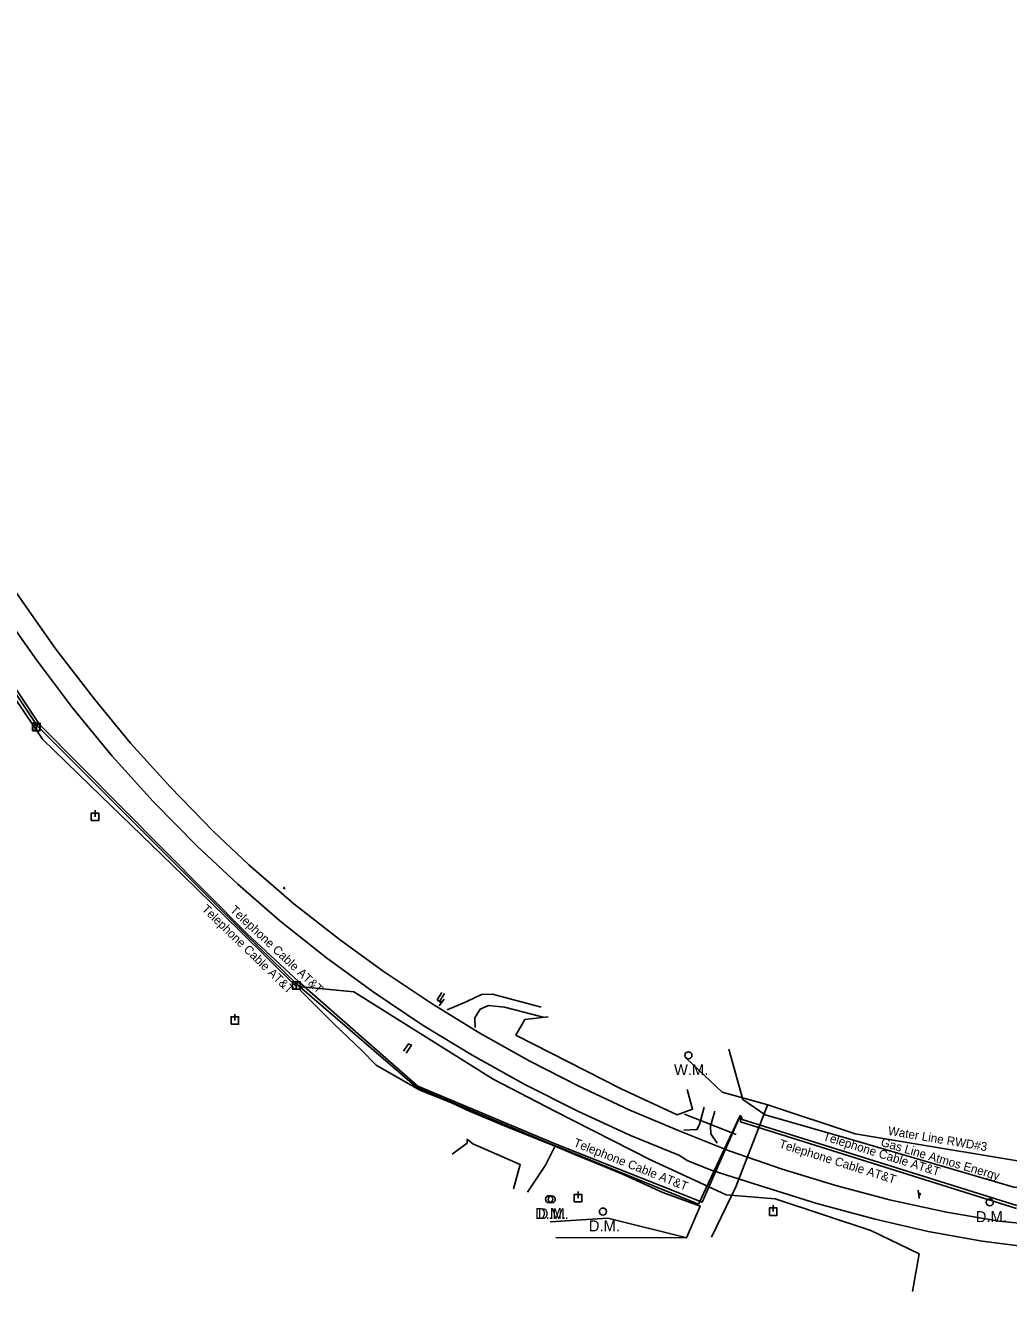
# Model space of a CAD drawing. Extents: x 19405533 to 19432306, y 137070 to 200991.
# Drawn here: x 19429869 to 19430925, y 137298 to 138658 of the extents above; entities that cross this region are included whole.
import ezdxf

# ---------------------------------------------------------------- set-up
doc = ezdxf.new("R2010")
doc.units = 0
for name, color, linetype in [('sv_Drainage Structures_x_s', 7, 'Continuous'), ('sv_Fence Existing_x_s', 7, 'Continuous'), ('sv_Gas Utility Label_x_n', 7, 'Continuous'), ('sv_Gas Utility_x_n', 7, 'Continuous'), ('sv_Pavement Edge_x_s', 7, 'Continuous'), ('sv_Poles Utility_x_n', 7, 'Continuous'), ('sv_Private Road_x_s', 7, 'Continuous'), ('sv_Signs Billboards_x_s', 7, 'Continuous'), ('sv_Slope Lines_x_s', 7, 'Continuous'), ('sv_Telephone Line Label_x_n', 7, 'Continuous'), ('sv_Telephone Line_x_n', 7, 'Continuous'), ('sv_Treeline_x_s', 7, 'Continuous'), ('sv_Water Line Label_x_n', 7, 'Continuous'), ('sv_Water Line_x_n', 7, 'Continuous'), ('sv_Waters Edge_x_s', 7, 'Continuous')]:
    doc.layers.add(name, color=color, linetype=linetype)

msp = doc.modelspace()

# ---------------------------------------------------------------- linework, layer by layer
at = {"layer": 'sv_Drainage Structures_x_s'}
msp.add_line((19430632.3, 137466.8), (19430577, 137488.7), dxfattribs=at)
for points in [[(19430147.7, 137732.2), (19430146.7, 137732.1), (19430146.8, 137730.9), (19430148, 137731.1)], [(19430147.7, 137732.2), (19430146.7, 137732.1), (19430146.8, 137730.9), (19430148, 137731.1)], [(19430147.7, 137732.2), (19430146.7, 137732.1), (19430146.8, 137730.9), (19430148, 137731.1)], [(19430319.3, 137618.4), (19430313.9, 137609.8), (19430311.4, 137611.5), (19430316.2, 137619.4)], [(19430319.3, 137618.4), (19430313.9, 137609.8), (19430311.4, 137611.5), (19430316.2, 137619.4)], [(19430319.3, 137618.4), (19430313.9, 137609.8), (19430311.4, 137611.5), (19430316.2, 137619.4)], [(19430275.1, 137556.2), (19430280.6, 137564.3), (19430283.7, 137562.9), (19430278.1, 137554.3)]]:
    msp.add_lwpolyline(points, dxfattribs=at)
at = {"layer": 'sv_Fence Existing_x_s'}
msp.add_line((19430438.8, 137356), (19430579.5, 137355.6), dxfattribs=at)
for points in [[(19430161.1, 137624.8), (19430099.2, 137685.4), (19430038.4, 137744.9), (19429938.2, 137841.9), (19429887.5, 137891.4), (19429856.8, 137936.6), (19429776.8, 138056.5), (19429730.3, 138127.7)], [(19430162.4, 137623.5), (19430200.2, 137585.8), (19430229.9, 137557.4), (19430245.9, 137541.3), (19430292.7, 137514.5), (19430326.6, 137500.8), (19430326.6, 137500.8), (19430346.7, 137491.4), (19430388, 137474.2), (19430417.3, 137462.5), (19430438, 137454.2), (19430458.2, 137445.8), (19430480.9, 137436.2), (19430509.7, 137424.5), (19430553.8, 137404.4), (19430593.8, 137389.9), (19430579.3, 137355.7)]]:
    msp.add_lwpolyline(points, dxfattribs=at)
at = {"layer": 'sv_Gas Utility_x_n'}
msp.add_lwpolyline([(19432037.6, 137379.6), (19431571.4, 137393.9), (19430996.6, 137402.9), (19430930.7, 137410.1), (19430758.5, 137460.5), (19430663.5, 137488), (19430639.7, 137504.2), (19430624.7, 137558.5)], dxfattribs=at)
msp.add_lwpolyline([(19432037.6, 137379.6), (19431571.4, 137393.9), (19430996.6, 137402.9), (19430930.7, 137410.1), (19430758.5, 137460.5), (19430663.5, 137488), (19430639.7, 137504.2), (19430624.7, 137558.5)], dxfattribs=at)
msp.add_lwpolyline([(19432037.6, 137379.6), (19431571.4, 137393.9), (19430996.6, 137402.9), (19430930.7, 137410.1), (19430758.5, 137460.5), (19430663.5, 137488), (19430639.7, 137504.2), (19430624.7, 137558.5)], dxfattribs=at)
at = {"layer": 'sv_Pavement Edge_x_s'}
for points in [[(19429459.1, 138633.6), (19429496.2, 138578.8), (19429532.9, 138525), (19429569.7, 138471.2), (19429607.7, 138415.4), (19429642, 138365.4), (19429644.7, 138364), (19429686.6, 138301.7), (19429688.3, 138297.5), (19429724.6, 138242.8), (19429763.6, 138186.4), (19429792.8, 138143.7), (19429829.4, 138091.6), (19429865.5, 138039.6), (19429901.9, 137988.3), (19429943.3, 137934.4), (19429982.1, 137887.3), (19430024.5, 137840.1), (19430070.7, 137792.6), (19430109, 137756.6)], [(19430053.5, 137776.4), (19430006.1, 137824.5), (19429962.2, 137873.1), (19429919.8, 137925), (19429881, 137976.7), (19429843.6, 138029.5), (19429805, 138084.7), (19429774.6, 138127.7), (19429764.8, 138139.4), (19429738.2, 138178.1), (19429735.7, 138184.8), (19429699.6, 138238.3), (19429665.1, 138289.8), (19429624.4, 138349.5), (19429586.7, 138404.5), (19429549.8, 138458.9), (19429515.2, 138509.9), (19429480.2, 138560.9), (19429438.8, 138621.4)], [(19430955.9, 137344.5), (19430896.8, 137352.3), (19430838.8, 137362.5), (19430781.7, 137375.7), (19430719.1, 137392.7), (19430658.5, 137411.6), (19430606.8, 137428), (19430580.7, 137438.5), (19430570.8, 137444.4), (19430519, 137465.7), (19430462.3, 137491.8), (19430404.6, 137520.8), (19430349.7, 137551.8), (19430296.3, 137584), (19430242.5, 137620.2), (19430192.6, 137656.7), (19430142.4, 137696.4), (19430097.1, 137735.7), (19430053.5, 137776.4)], [(19430109, 137756.6), (19430157.5, 137714.6), (19430207.6, 137675.6), (19430253.3, 137642.2), (19430306.1, 137607), (19430357.3, 137575.5), (19430410.8, 137545.6), (19430462.6, 137519.1), (19430518.1, 137492.8), (19430571.1, 137470.7), (19430625.1, 137449.2), (19430682, 137429.6), (19430739.6, 137411.9), (19430797.1, 137396.7), (19430858.3, 137383.3), (19430914.9, 137373.7), (19430957.8, 137369.5)]]:
    msp.add_lwpolyline(points, dxfattribs=at)
at = {"layer": 'sv_Poles Utility_x_n'}
for p, q in [((19429939.8, 137812), (19429939.9, 137812.1)), ((19429943.8, 137808.1), (19429943.8, 137815.1)), ((19430090, 137593.1), (19430090.1, 137593.2)), ((19430094, 137589.2), (19430094, 137596.2)), ((19430458.6, 137402.3), (19430458.7, 137402.4)), ((19430462.6, 137398.4), (19430462.6, 137405.5)), ((19430668.3, 137387.7), (19430668.4, 137387.8)), ((19430672.3, 137383.9), (19430672.3, 137390.9))]:
    msp.add_line(p, q, dxfattribs=at)
for points in [[(19429939.8, 137804.1), (19429947.8, 137804.1), (19429947.8, 137812.1), (19429939.8, 137812.1)], [(19430090, 137585.2), (19430098, 137585.2), (19430098, 137593.2), (19430090, 137593.2)], [(19430458.6, 137394.4), (19430466.6, 137394.4), (19430466.6, 137402.4), (19430458.6, 137402.4)], [(19430668.3, 137379.8), (19430676.3, 137379.8), (19430676.3, 137387.8), (19430668.3, 137387.8)]]:
    msp.add_lwpolyline(points, close=True, dxfattribs=at)
for centre in [(19430431.6, 137397.2), (19430434.4, 137397.1), (19430489.3, 137384), (19430904.9, 137393.9)]:
    msp.add_circle(centre, 3.78, dxfattribs=at)
at = {"layer": 'sv_Private Road_x_s'}
for points in [[(19430422.9, 137603.7), (19430370.8, 137617.4), (19430359, 137617.1), (19430343.3, 137609.6), (19430322.1, 137600.6)], [(19430422.9, 137603.7), (19430370.8, 137617.4), (19430359, 137617.1), (19430343.3, 137609.6), (19430322.1, 137600.6)], [(19430422.9, 137603.7), (19430370.8, 137617.4), (19430359, 137617.1), (19430343.3, 137609.6), (19430322.1, 137600.6)], [(19430352, 137581.7), (19430351.8, 137592.1), (19430357.4, 137601.5), (19430366.5, 137605.5), (19430383.8, 137603.5), (19430425, 137592.7)], [(19430352, 137581.7), (19430351.8, 137592.1), (19430357.4, 137601.5), (19430366.5, 137605.5), (19430383.8, 137603.5), (19430425, 137592.7)], [(19430352, 137581.7), (19430351.8, 137592.1), (19430357.4, 137601.5), (19430366.5, 137605.5), (19430383.8, 137603.5), (19430425, 137592.7)], [(19430598.1, 137496), (19430593.2, 137477.5), (19430590.3, 137472.2), (19430576.3, 137471.3)], [(19430598.1, 137496), (19430593.2, 137477.5), (19430590.3, 137472.2), (19430576.3, 137471.3)], [(19430598.1, 137496), (19430593.2, 137477.5), (19430590.3, 137472.2), (19430576.3, 137471.3)], [(19430609.4, 137491.8), (19430604.9, 137475.7), (19430605.1, 137467.5), (19430612.1, 137457.6)], [(19430609.4, 137491.8), (19430604.9, 137475.7), (19430605.1, 137467.5), (19430612.1, 137457.6)], [(19430609.4, 137491.8), (19430604.9, 137475.7), (19430605.1, 137467.5), (19430612.1, 137457.6)]]:
    msp.add_lwpolyline(points, dxfattribs=at)
at = {"layer": 'sv_Signs Billboards_x_s'}
for p, q in [((19430313.6, 137604.9), (19430318.8, 137612.1)), ((19430828.1, 137406.9), (19430828.9, 137398.1))]:
    msp.add_line(p, q, dxfattribs=at)
for centre in [(19430315.5, 137609), (19430829.4, 137402.6)]:
    msp.add_circle(centre, 0.885, dxfattribs=at)
at = {"layer": 'sv_Slope Lines_x_s'}
msp.add_lwpolyline([(19430437.3, 137453.1), (19430427.6, 137433.8), (19430408.2, 137404.8)], dxfattribs=at)
at = {"layer": 'sv_Telephone Line_x_n'}
for points in [[(19427230.2, 142026.5), (19427510.2, 141439), (19427571.8, 141314.8), (19428025.4, 140631.5), (19428873.9, 139386.4), (19429185.4, 138929.1), (19429541.8, 138410.7), (19429732.8, 138129.1), (19429881.9, 137905.4), (19430105.7, 137681.5), (19430161, 137628), (19430289.6, 137517.3), (19430437.1, 137455.1)], [(19427230.2, 142026.5), (19427510.2, 141439), (19427571.8, 141314.8), (19428025.4, 140631.5), (19428873.9, 139386.4), (19429185.4, 138929.1), (19429541.8, 138410.7), (19429732.8, 138129.1), (19429881.9, 137905.4), (19430105.7, 137681.5), (19430161, 137628), (19430289.6, 137517.3), (19430437.1, 137455.1)], [(19427230.2, 142026.5), (19427510.2, 141439), (19427571.8, 141314.8), (19428025.4, 140631.5), (19428873.9, 139386.4), (19429185.4, 138929.1), (19429541.8, 138410.7), (19429732.8, 138129.1), (19429881.9, 137905.4), (19430105.7, 137681.5), (19430161, 137628), (19430289.6, 137517.3), (19430437.1, 137455.1)], [(19427232.6, 142026.7), (19427516.6, 141441.9), (19427576.5, 141318.9), (19428030.9, 140635.7), (19428875.6, 139387.9), (19429188.7, 138931.7), (19429544.4, 138412.7), (19429735.8, 138130.4), (19429884.2, 137907.1), (19430107.4, 137682.5), (19430162.7, 137630.6), (19430290.4, 137518.7), (19430437.9, 137456.9)], [(19427232.6, 142026.7), (19427516.6, 141441.9), (19427576.5, 141318.9), (19428030.9, 140635.7), (19428875.6, 139387.9), (19429188.7, 138931.7), (19429544.4, 138412.7), (19429735.8, 138130.4), (19429884.2, 137907.1), (19430107.4, 137682.5), (19430162.7, 137630.6), (19430290.4, 137518.7), (19430437.9, 137456.9)], [(19427232.6, 142026.7), (19427516.6, 141441.9), (19427576.5, 141318.9), (19428030.9, 140635.7), (19428875.6, 139387.9), (19429188.7, 138931.7), (19429544.4, 138412.7), (19429735.8, 138130.4), (19429884.2, 137907.1), (19430107.4, 137682.5), (19430162.7, 137630.6), (19430290.4, 137518.7), (19430437.9, 137456.9)], [(19429878.6, 137906.8), (19429882.7, 137906.8), (19429880.7, 137906.8), (19429880.7, 137900.6), (19429876.7, 137900.6), (19429876.7, 137908.6), (19429884.7, 137908.6), (19429884.7, 137900.6), (19429880.7, 137900.6)], [(19429878.8, 137907.1), (19429882.9, 137907.1), (19429880.9, 137907.1), (19429880.9, 137900.8), (19429876.9, 137900.8), (19429876.9, 137908.8), (19429884.9, 137908.8), (19429884.9, 137900.8), (19429880.9, 137900.8)], [(19430158, 137629), (19430162, 137629), (19430160, 137629), (19430160, 137622.8), (19430156, 137622.8), (19430156, 137630.8), (19430164, 137630.8), (19430164, 137622.8), (19430160, 137622.8)], [(19430636.3, 137486.6), (19430592, 137391.8), (19430437.4, 137455)], [(19430637.1, 137487.7), (19430596.1, 137394.1), (19430438.2, 137456.7)], [(19430933.5, 137387.4), (19430637.2, 137480.5), (19430636.8, 137486.6)], [(19430933.9, 137390.6), (19430638.9, 137482.8), (19430637.4, 137486.7)]]:
    msp.add_lwpolyline(points, dxfattribs=at)
at = {"layer": 'sv_Treeline_x_s'}
for points in [[(19430162.4, 137625.7), (19430221.7, 137620.2), (19430371.4, 137526.3), (19430437.6, 137491.7), (19430540.3, 137439.4), (19430621.8, 137402.1), (19430674.4, 137397.7), (19430777, 137363.6), (19430828.9, 137338.5), (19430821.7, 137297.9)], [(19430579.7, 137515), (19430585.6, 137494.1), (19430569.1, 137488), (19430508.9, 137515.7), (19430395.9, 137573.5), (19430405.5, 137590.4), (19430430.4, 137593.2)], [(19430579.7, 137515), (19430585.6, 137494.1), (19430569.1, 137488), (19430508.9, 137515.7), (19430395.9, 137573.5), (19430405.5, 137590.4), (19430430.4, 137593.2)], [(19430579.7, 137515), (19430585.6, 137494.1), (19430569.1, 137488), (19430508.9, 137515.7), (19430395.9, 137573.5), (19430405.5, 137590.4), (19430430.4, 137593.2)], [(19430432.6, 137373.1), (19430494.7, 137376.9), (19430579.5, 137355.8)]]:
    msp.add_lwpolyline(points, dxfattribs=at)
at = {"layer": 'sv_Water Line_x_n'}
for points in [[(19432027.6, 137384.4), (19431576.3, 137414.6), (19430990.4, 137429), (19430760.2, 137467.5), (19430666.4, 137498.8), (19430617.6, 137512.2), (19430579, 137548.3)], [(19432027.6, 137384.4), (19431576.3, 137414.6), (19430990.4, 137429), (19430760.2, 137467.5), (19430666.4, 137498.8), (19430617.6, 137512.2), (19430579, 137548.3)], [(19432027.6, 137384.4), (19431576.3, 137414.6), (19430990.4, 137429), (19430760.2, 137467.5), (19430666.4, 137498.8), (19430617.6, 137512.2), (19430579, 137548.3)], [(19430666.3, 137498.2), (19430632, 137410.4), (19430605.8, 137356.4)], [(19430666.3, 137498.2), (19430632, 137410.4), (19430605.8, 137356.4)], [(19430666.3, 137498.2), (19430632, 137410.4), (19430605.8, 137356.4)]]:
    msp.add_lwpolyline(points, dxfattribs=at)
msp.add_circle((19430581.2, 137551.8), 3.78, dxfattribs=at)
at = {"layer": 'sv_Waters Edge_x_s'}
msp.add_lwpolyline([(19430327.5, 137445.5), (19430343.6, 137457.5), (19430343.6, 137461.7), (19430349.6, 137456.7), (19430400.5, 137434.4), (19430393.4, 137408.5)], dxfattribs=at)

# ---------------------------------------------------------------- texts
at = {"layer": 'sv_Gas Utility Label_x_n'}
msp.add_text('Gas Line Atmos Energy', height=9.35, rotation=343.6709, dxfattribs=at).set_placement((19430787.1, 137454.6))
at = {"layer": 'sv_Poles Utility_x_n'}
for p in [(19430416.5, 137376), (19430419.4, 137375.8), (19430474.3, 137362.7), (19430889.9, 137372.6)]:
    msp.add_text('D.M.', height=11.8, dxfattribs=at).set_placement(p)
at = {"layer": 'sv_Telephone Line Label_x_n'}
for rotation, p in [(315.9864, (19430057.8, 137708.1)), (316.8105, (19430088.2, 137707)), (342.6446, (19430725, 137461)), (338.3789, (19430457, 137454.4)), (342.5497, (19430677.8, 137452.9))]:
    msp.add_text('Telephone Cable AT&T', height=9.35, rotation=rotation, dxfattribs=at).set_placement(p)
at = {"layer": 'sv_Water Line Label_x_n'}
msp.add_text('Water Line RWD#3', height=9.35, rotation=350.5216, dxfattribs=at).set_placement((19430795, 137466.5))
at = {"layer": 'sv_Water Line_x_n'}
msp.add_text('W.M.', height=11.8, dxfattribs=at).set_placement((19430565.7, 137530.5))

doc.saveas('drawing.dxf')
